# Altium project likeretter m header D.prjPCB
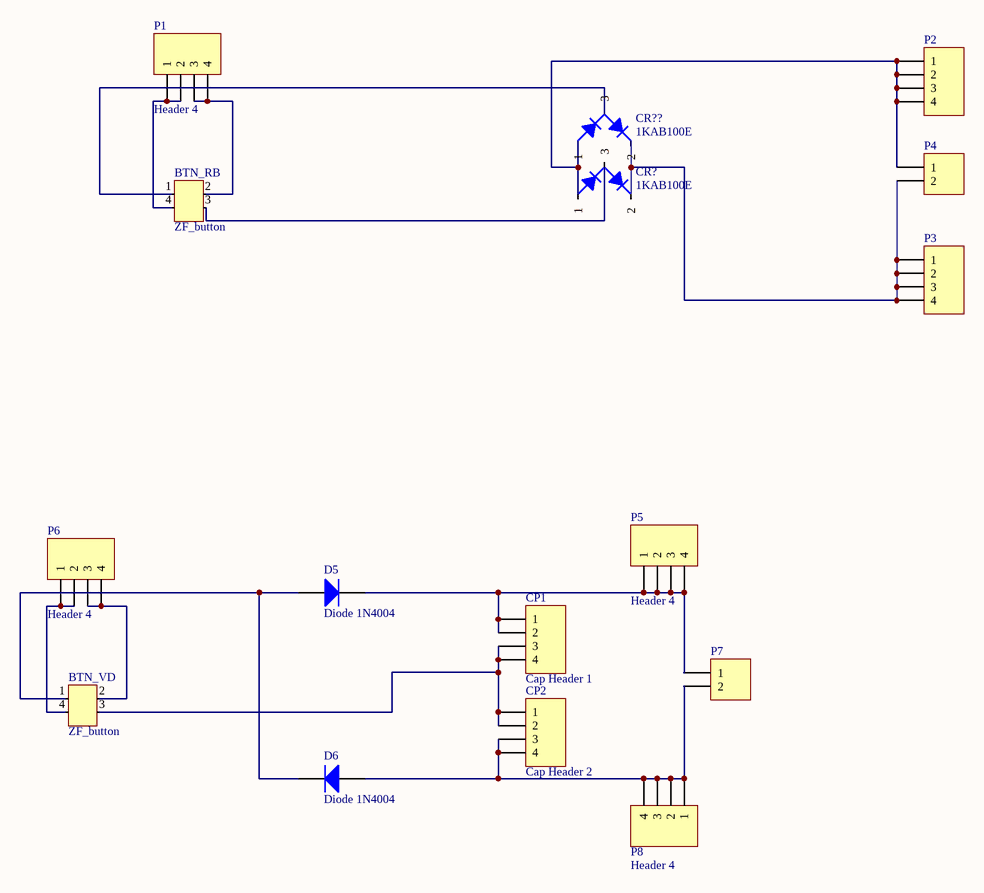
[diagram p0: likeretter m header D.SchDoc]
1 sheet, 16 parts. Net scope: global (net labels, ports and power ports of the same name join across sheets).
Board file: likeretter m header D.PcbDoc

## Sheet likeretter m header D.SchDoc
size A4

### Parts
BTN_RB  ZF_button  [ZF-button]
BTN_VD  ZF_button  [ZF-button]
CP1  Cap Header 1  [HDR1X4]
CP2  Cap Header 2  [HDR1X4]
CR?  1KAB100E  [SOT-23_N]
CR??  1KAB100E  [SOT-23_N]
D5  Diode 1N4004  [SOT-23_N]
D6  Diode 1N4004  [SOT23_N]
P1  Header 4  [HDR1X4]
P2  Header 4  [HDR1X4]  (value not drawn)
P3  Header 3  [HDR1X4]  (value not drawn)
P4  Header 2H  [HDR1X2H]  (value not drawn)
P5  Header 4  [HDR1X4]
P6  Header 4  [HDR1X4]
P7  Header 2H  [HDR1X2H]  (value not drawn)
P8  Header 4  [HDR1X4]

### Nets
NetBTN_RB_1: BTN_RB.1 CR??.3
NetBTN_RB_2: BTN_RB.2 P1.3 P1.4
NetBTN_RB_3: BTN_RB.3 CR?.3
NetBTN_RB_4: BTN_RB.4 P1.1 P1.2
NetBTN_VD_1: BTN_VD.1 D5.1(A) D6.2(K)
NetBTN_VD_2: BTN_VD.2 P6.3 P6.4
NetBTN_VD_3: BTN_VD.3 CP1.3 CP1.4 CP2.1 CP2.2
NetBTN_VD_4: BTN_VD.4 P6.1 P6.2
NetCP1_1: CP1.1 CP1.2 D5.2(K) P5.1 P5.2 P5.3 P5.4 P7.1
NetCP2_3: CP2.3 CP2.4 D6.1(A) P7.2 P8.1 P8.2 P8.3 P8.4
NetCR?_1: CR?.1(2) CR??.1(2) P3.1 P3.2 P3.3 P3.4 P4.2
NetCR?_2: CR?.2(1) CR??.2(1) P2.1 P2.2 P2.3 P2.4 P4.1

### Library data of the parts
CP1 CP2 P1-P3 P5 P6 P8 = Header 4: Header, 4-Pin
CR? CR?? = 1KAB100E: 1.2 Amp Rectifier Bridge
D5 D6 = Diode 1N4004: 1 Amp General Purpose Rectifier; pin to pad: 2>3
P4 P7 = Header 2H: Header, 2-Pin, Right Angle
